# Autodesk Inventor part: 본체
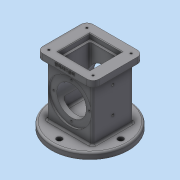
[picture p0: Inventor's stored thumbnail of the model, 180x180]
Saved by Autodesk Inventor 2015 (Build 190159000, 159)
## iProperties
Created: 2018-10
Part Number: 본체
Material: 알루미늄 6061
Document SubType Name: Modeling
Designer: SCD-A02
Density: 2.7 g/cm^3
Appearance: 기본값
Mass: 986.278 g
Surface Area: 748.205 cm^2
Volume: 365.288 cm^3
Author: SCD-A02
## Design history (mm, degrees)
sketch "스케치1"
  geometry: C1 r 62.5 at (0, 0); 1 further point
  constraints: 1 centre point, 1 coincident
  dimensions: "d0" = 125 diameter of C1
extrude "돌출1" new body sketch "스케치1" distance "d1" = 10; taper "d2" = 0 deg
sketch "스케치2"
  geometry: L1 (-37, 33)-(37, 33); L2 (37, 33)-(37, -33); L3 (37, -33)-(-37, -33); L4 (-37, -33)-(-37, 33); C1 r 62.5 at (0, 0) reference; 2 further points
  constraints: 8 end point, 2 midpoint, 2 parallel, 1 horizontal, 1 horizontal alignment, 1 perpendicular, 1 vertical alignment
  dimensions: "d3" = 74 distance of L1.start L1.end; "d4" = 66 distance of L3.end L1.start
extrude "돌출2" join sketch "스케치2" distance "d5" = 88; taper "d6" = 0 deg
sketch "스케치3"
  geometry: L1 (-46, 41)-(46, 41); L2 (46, 41)-(46, -41); L3 (46, -41)-(-46, -41); L4 (-46, -41)-(-46, 41); 3 further points
  constraints: 8 end point, 2 midpoint, 2 parallel, 1 horizontal, 1 horizontal alignment, 1 perpendicular, 1 vertical alignment
  dimensions: "d7" = 92 distance of L1.start L1.end; "d8" = 82 distance of L3.end L1.start
extrude "돌출3" join sketch "스케치3" distance "d9" = 10; taper "d10" = 0 deg
sketch "스케치4"
  geometry: L1 (0, 10)-(92, 10) reference; L2 (0, 0)-(0, 10) reference; 2 further points
  constraints: 1 other
  dimensions: "d11" = 46 distance from line of point (46, 6) L2; "d12" = 4 distance from line of L1 point (46, 6)
feature "엠보싱1" sketch "스케치4" dims "d13" = 0.5, "d14" = 0
sketch "스케치5"
  geometry: L1 (-62.5, 0)-(62.5, 0) reference; L2 (-33, 10)-(33, 10) reference; L3 (-33, 10)-(-33, 98) reference; L4 (33, 98)-(-33, 98) reference; L5 (33, 10)-(33, 98) reference; L6 (-54.976, 54)-(80.475, 54); L7 (-33, 54)-(-33, 78); L8 (33, 78)-(33, 54); L9 (33, 78)-(-33, 78); 1 further point
  constraints: 8 end point, 4 point on line, 2 horizontal, 2 midpoint
  dimensions: "d15" = 54 distance between parallel lines of L1 L6; "d16" = 48 diameter of L9 L6
revolve "회전1" sketch "스케치5" stored, may be unused: angle "d17" = 90 deg
sketch "스케치7"
  geometry: L1 (-26, 26)-(26, 26); L2 (26, 26)-(26, -26); L3 (26, -26)-(-26, -26); L4 (-26, -26)-(-26, 26); 3 further points
  constraints: 8 end point, 2 midpoint, 2 parallel, 2 perpendicular, 1 horizontal, 1 horizontal alignment, 1 vertical alignment
  dimensions: "d18" = 52 distance of L1.start L1.end
extrude "돌출4" cut sketch "스케치7" distance "d19" = 8; taper "d20" = 0 deg
sketch "스케치8"
  geometry: L1 (-22, 22)-(22, 22); L2 (22, 22)-(22, -22); L3 (22, -22)-(-22, -22); L4 (-22, -22)-(-22, 22); 3 further points
  constraints: 8 end point, 2 midpoint, 2 parallel, 2 perpendicular, 1 horizontal, 1 horizontal alignment, 1 vertical alignment
  dimensions: "d21" = 44 distance of L1.start L1.end
extrude "돌출5" cut sketch "스케치8" distance "d22" = 74; taper "d23" = 0 deg
sketch "스케치9"
  geometry: C1 r 24 at (37, 44) reference; 2 further points
  constraints: 1 coincident
hole "구멍1" sketch "스케치9" at (37, 44) diameter "d24" = 70; stored, may be unused: countersink angle "d28" = 90 deg, drill point angle "d30" = 0 deg; dims "d25" = 7, "d26" = 4, "d27" = 2, "d29" = 3
sketch "스케치10"
  geometry: C1 r 24 at (37, -44) reference; 2 further points
  constraints: 1 coincident
hole "구멍2" sketch "스케치10" at (37, -44) diameter "d31" = 70; stored, may be unused: countersink angle "d35" = 90 deg, drill point angle "d37" = 0 deg; dims "d32" = 7, "d33" = 4, "d34" = 2, "d36" = 3
sketch "스케치11"
  geometry: C1 r 24 at (0, 0) reference; 2 further points
  constraints: 1 vertical alignment
  dimensions: "d38" = 29 distance of C1.centre point (0, 29)
hole "구멍3" sketch "스케치11" at (0, 29) diameter "d39" = 3.242; stored, may be unused: countersink angle "d43" = 90 deg, drill point angle "d45" = 118 deg; dims "d40" = 4, "d41" = 4, "d42" = 2, "d44" = 6
sketch "스케치12"
  geometry: C1 r 24 at (0, 0) reference; 2 further points
  constraints: 1 vertical alignment
  dimensions: "d49" = 29 distance of C1.centre point (0, -29)
hole "구멍4" sketch "스케치12" at (0, -29) diameter "d50" = 3.242; stored, may be unused: countersink angle "d54" = 90 deg, drill point angle "d56" = 118 deg; dims "d51" = 4, "d52" = 4, "d53" = 2, "d55" = 6
sketch "스케치13"
  geometry: C1 r 62.5 at (0, 0) reference; C2 r 28 at (0, 0)
  constraints: 1 centre point, 1 coincident
  dimensions: "d60" = 56 diameter of C2
extrude "돌출6" cut sketch "스케치13" distance "d61" = 18; taper "d62" = -10 deg
sketch "스케치14"
  geometry: C1 r 62.5 at (0, 0) reference; 1 further point
  constraints: 1 vertical alignment
  dimensions: "d64" = 50 distance of C1.centre point (0, -50)
hole "구멍5" sketch "스케치14" at (0, -50) diameter "d65" = 9; stored, may be unused: countersink angle "d69" = 90 deg, drill point angle "d71" = 0 deg; dims "d66" = 4, "d67" = 4, "d68" = 2, "d70" = 6
sketch "스케치15"
  geometry: 5 further points
  constraints: 2 horizontal alignment, 2 vertical alignment
  dimensions: "d77" = 62 distance of point (36, 31) point (36, -31); "d78" = 72 distance of point (-36, -31) point (36, -31); "d79" = 36 horizontal distance of point (0, 0) point (36, -31); "d80" = 31 vertical distance of point (0, 0) point (36, -31)
hole "구멍6" sketch "스케치15" at (36, -31), (-36, -31), (-36, 31), (36, 31) diameter "d81" = 3.242; stored, may be unused: countersink angle "d85" = 90 deg, drill point angle "d87" = 118 deg; dims "d82" = 4, "d83" = 4, "d84" = 2, "d86" = 6
sketch "스케치16"
  geometry: L1 (10, -29.5)-(10, 95.5) reference; 3 further points
  constraints: 2 horizontal alignment
  dimensions: "d88" = 37 distance from line of L1 point (-27, 33); "d89" = 43 distance of point (-27, 33) point (-70, 33)
hole "구멍7" sketch "스케치16" at (-70, 33), (-27, 33) diameter "d90" = 4.134; stored, may be unused: countersink angle "d94" = 90 deg, drill point angle "d96" = 0 deg; dims "d91" = 15, "d92" = 4, "d93" = 2, "d95" = 15
fillet "모깎기1" dims "d97" = 10
fillet "모깎기2" dims "d98" = 10
fillet "모깎기3" dims "d99" = 3
fillet "모깎기4" dims "d100" = 3
fillet "모깎기5" dims "d101" = 3
fillet "모깎기6" dims "d102" = 3
chamfer "모따기1" distance "d103" = 1; stored, may be unused: second distance "d104" = 2, angle "d105" = 45 deg
fillet "모깎기7" dims "d106" = 3
fillet "모깎기8" dims "d107" = 3
node "솔리드1"
pattern_circular "원형 패턴1" dims angle "d47" = 360 deg
pattern_circular "원형 패턴2" dims angle "d58" = 360 deg
pattern_circular "원형 패턴3" dims angle "d73" = 360 deg
node "투영된 루프1"
